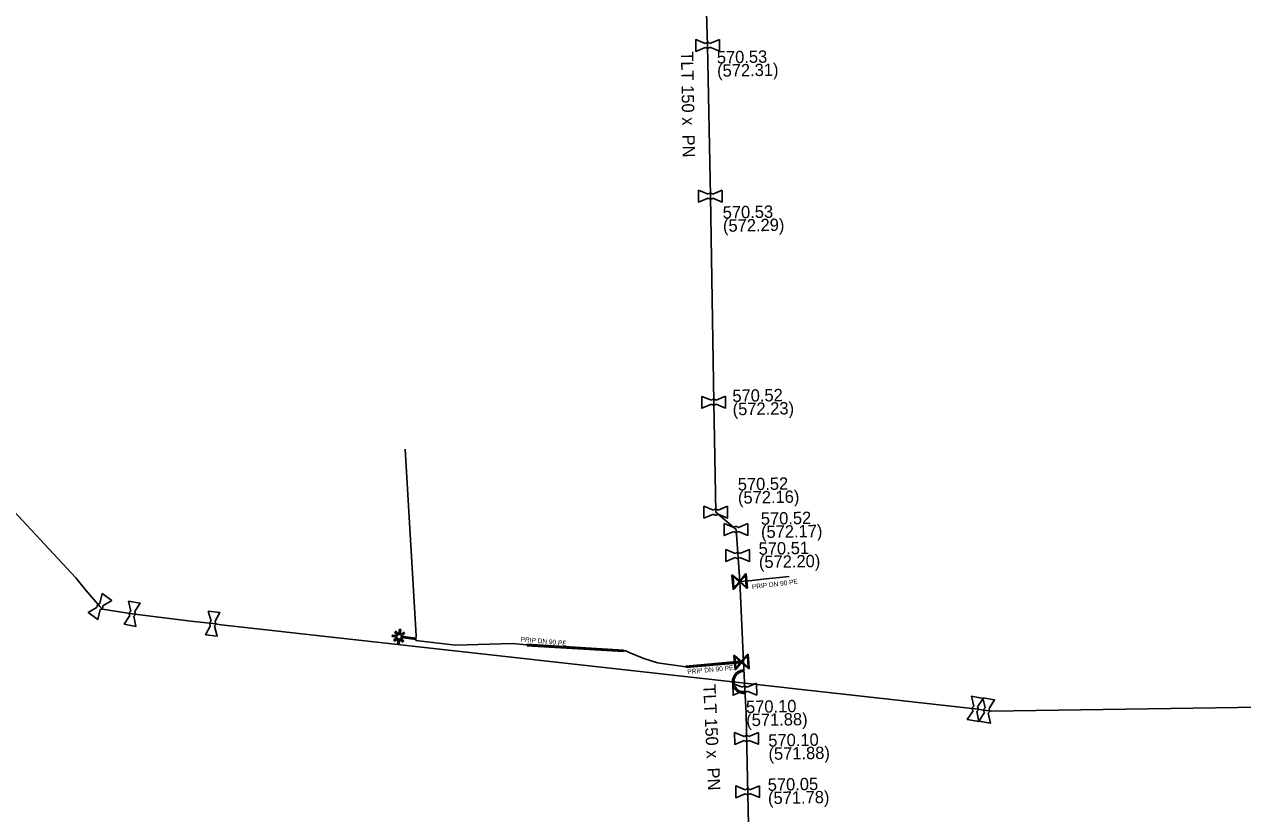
# Model space of a CAD drawing. Extents: x -643544 to -637295, y -1119190 to -1111715.
# Drawn here: x -641643.9 to -641515.4, y -1114531.6 to -1114448.4 of the extents above; entities that cross this region are included whole.
import ezdxf

# ---------------------------------------------------------------- set-up
doc = ezdxf.new("R2010")
doc.units = 0
for name, color, linetype in [('Default', 7, 'Continuous'), ('VP Chránička', 7, 'Continuous'), ('VP Chránička - okraje', 7, 'Continuous'), ('VP Lomový bod', 7, 'Continuous'), ('VP Lomový bod - popis', 7, 'Continuous'), ('VP Nepropojené křížení', 7, 'Continuous'), ('VP Popis přípojky', 7, 'Continuous'), ('VP Přípojka', 7, 'Continuous'), ('VP Změna materiálu', 7, 'Continuous'), ('VP Řad', 7, 'Continuous'), ('VP Řad - popis', 7, 'Continuous'), ('VP Šoupě', 7, 'Continuous')]:
    doc.layers.add(name, color=color, linetype=linetype)

msp = doc.modelspace()

# ---------------------------------------------------------------- linework, layer by layer
at = {"layer": 'Default'}
for points in [[(-641572.12, -1114450.39), (-641572.08, -1114450.35), (-641572.04, -1114450.32), (-641571.96, -1114450.28), (-641571.88, -1114450.28), (-641571.8, -1114450.28), (-641571.72, -1114450.32), (-641571.68, -1114450.34), (-641571.64, -1114450.38)], [(-641571.64, -1114450.79), (-641571.67, -1114450.83), (-641571.72, -1114450.86), (-641571.8, -1114450.9), (-641571.88, -1114450.9), (-641571.96, -1114450.9), (-641572.03, -1114450.86), (-641572.08, -1114450.84), (-641572.12, -1114450.8)], [(-641571.81, -1114466.29), (-641571.77, -1114466.25), (-641571.73, -1114466.22), (-641571.65, -1114466.18), (-641571.57, -1114466.18), (-641571.49, -1114466.18), (-641571.41, -1114466.22), (-641571.37, -1114466.24), (-641571.33, -1114466.28)], [(-641571.33, -1114466.69), (-641571.36, -1114466.73), (-641571.41, -1114466.76), (-641571.49, -1114466.8), (-641571.57, -1114466.8), (-641571.65, -1114466.8), (-641571.72, -1114466.76), (-641571.77, -1114466.74), (-641571.81, -1114466.7)], [(-641571.46, -1114488.03), (-641571.42, -1114487.99), (-641571.38, -1114487.96), (-641571.3, -1114487.92), (-641571.22, -1114487.92), (-641571.14, -1114487.92), (-641571.06, -1114487.96), (-641571.02, -1114487.98), (-641570.98, -1114488.02)], [(-641570.98, -1114488.43), (-641571.01, -1114488.47), (-641571.06, -1114488.5), (-641571.14, -1114488.54), (-641571.22, -1114488.54), (-641571.3, -1114488.54), (-641571.37, -1114488.5), (-641571.42, -1114488.48), (-641571.46, -1114488.44)], [(-641571.25, -1114499.63), (-641571.21, -1114499.59), (-641571.17, -1114499.56), (-641571.09, -1114499.52), (-641571.01, -1114499.52), (-641570.93, -1114499.52), (-641570.85, -1114499.56), (-641570.81, -1114499.58), (-641570.77, -1114499.62)], [(-641570.77, -1114500.03), (-641570.8, -1114500.07), (-641570.85, -1114500.1), (-641570.93, -1114500.14), (-641571.01, -1114500.14), (-641571.09, -1114500.14), (-641571.16, -1114500.1), (-641571.21, -1114500.08), (-641571.25, -1114500.04)], [(-641569.11, -1114501.46), (-641569.07, -1114501.42), (-641569.03, -1114501.39), (-641568.95, -1114501.35), (-641568.87, -1114501.35), (-641568.79, -1114501.35), (-641568.71, -1114501.39), (-641568.67, -1114501.41), (-641568.63, -1114501.45)], [(-641568.63, -1114501.86), (-641568.66, -1114501.9), (-641568.71, -1114501.93), (-641568.79, -1114501.97), (-641568.87, -1114501.97), (-641568.95, -1114501.97), (-641569.02, -1114501.93), (-641569.07, -1114501.91), (-641569.11, -1114501.87)], [(-641568.95, -1114504.2), (-641568.91, -1114504.16), (-641568.87, -1114504.13), (-641568.79, -1114504.09), (-641568.71, -1114504.09), (-641568.63, -1114504.09), (-641568.55, -1114504.13), (-641568.51, -1114504.15), (-641568.47, -1114504.19)], [(-641568.47, -1114504.6), (-641568.5, -1114504.64), (-641568.55, -1114504.67), (-641568.63, -1114504.71), (-641568.71, -1114504.71), (-641568.79, -1114504.71), (-641568.86, -1114504.67), (-641568.91, -1114504.65), (-641568.95, -1114504.61)], [(-641636.26, -1114509.85), (-641636.28, -1114509.8), (-641636.27, -1114509.75), (-641636.26, -1114509.66), (-641636.21, -1114509.6), (-641636.16, -1114509.53), (-641636.09, -1114509.49), (-641636.04, -1114509.47), (-641635.98, -1114509.47)], [(-641635.65, -1114509.71), (-641635.64, -1114509.76), (-641635.65, -1114509.81), (-641635.66, -1114509.9), (-641635.71, -1114509.96), (-641635.76, -1114510.03), (-641635.83, -1114510.06), (-641635.88, -1114510.09), (-641635.93, -1114510.09)], [(-641632.8, -1114510.74), (-641632.84, -1114510.69), (-641632.85, -1114510.64), (-641632.88, -1114510.56), (-641632.87, -1114510.48), (-641632.85, -1114510.4), (-641632.8, -1114510.34), (-641632.76, -1114510.29), (-641632.72, -1114510.27)], [(-641632.31, -1114510.34), (-641632.28, -1114510.38), (-641632.26, -1114510.43), (-641632.24, -1114510.52), (-641632.25, -1114510.6), (-641632.27, -1114510.68), (-641632.32, -1114510.74), (-641632.36, -1114510.78), (-641632.4, -1114510.81)], [(-641624.3, -1114511.8), (-641624.34, -1114511.76), (-641624.36, -1114511.71), (-641624.39, -1114511.64), (-641624.38, -1114511.55), (-641624.37, -1114511.47), (-641624.32, -1114511.4), (-641624.29, -1114511.36), (-641624.25, -1114511.33)], [(-641623.84, -1114511.38), (-641623.8, -1114511.42), (-641623.78, -1114511.46), (-641623.75, -1114511.54), (-641623.76, -1114511.63), (-641623.77, -1114511.71), (-641623.82, -1114511.77), (-641623.85, -1114511.82), (-641623.89, -1114511.85)], [(-641567.92, -1114518.96), (-641568.25, -1114518.98), (-641568.56, -1114518.83), (-641568.87, -1114518.68), (-641569.05, -1114518.39), (-641569.22, -1114518.1), (-641569.24, -1114517.78), (-641569.26, -1114517.47), (-641569.11, -1114517.16), (-641568.97, -1114516.85), (-641568.68, -1114516.67), (-641568.39, -1114516.48), (-641568.06, -1114516.47)], [(-641568.05, -1114516.62), (-641568.34, -1114516.64), (-641568.59, -1114516.8), (-641568.85, -1114516.96), (-641568.97, -1114517.23), (-641569.1, -1114517.5), (-641569.08, -1114517.77), (-641569.07, -1114518.05), (-641568.91, -1114518.3), (-641568.76, -1114518.56), (-641568.49, -1114518.69), (-641568.22, -1114518.82), (-641567.93, -1114518.81)], [(-641568.19, -1114518.3), (-641568.15, -1114518.26), (-641568.11, -1114518.23), (-641568.03, -1114518.19), (-641567.95, -1114518.19), (-641567.87, -1114518.19), (-641567.79, -1114518.23), (-641567.75, -1114518.26), (-641567.71, -1114518.3)], [(-641567.71, -1114518.71), (-641567.74, -1114518.75), (-641567.79, -1114518.77), (-641567.87, -1114518.81), (-641567.95, -1114518.82), (-641568.03, -1114518.82), (-641568.1, -1114518.77), (-641568.15, -1114518.75), (-641568.18, -1114518.71)], [(-641543.88, -1114520.78), (-641543.92, -1114520.73), (-641543.93, -1114520.68), (-641543.96, -1114520.6), (-641543.95, -1114520.52), (-641543.93, -1114520.44), (-641543.88, -1114520.38), (-641543.84, -1114520.33), (-641543.8, -1114520.31)], [(-641543.39, -1114520.38), (-641543.36, -1114520.42), (-641543.34, -1114520.47), (-641543.32, -1114520.56), (-641543.33, -1114520.64), (-641543.35, -1114520.72), (-641543.4, -1114520.78), (-641543.44, -1114520.82), (-641543.48, -1114520.85)], [(-641542.68, -1114520.95), (-641542.72, -1114520.9), (-641542.73, -1114520.85), (-641542.76, -1114520.77), (-641542.75, -1114520.69), (-641542.73, -1114520.61), (-641542.68, -1114520.55), (-641542.64, -1114520.5), (-641542.6, -1114520.48)], [(-641542.19, -1114520.55), (-641542.16, -1114520.59), (-641542.14, -1114520.64), (-641542.12, -1114520.73), (-641542.13, -1114520.81), (-641542.15, -1114520.89), (-641542.2, -1114520.95), (-641542.24, -1114520.99), (-641542.28, -1114521.02)], [(-641568, -1114523.5), (-641567.97, -1114523.46), (-641567.92, -1114523.43), (-641567.85, -1114523.39), (-641567.77, -1114523.39), (-641567.68, -1114523.39), (-641567.61, -1114523.43), (-641567.56, -1114523.45), (-641567.53, -1114523.49)], [(-641567.52, -1114523.9), (-641567.56, -1114523.94), (-641567.6, -1114523.97), (-641567.68, -1114524.01), (-641567.76, -1114524.01), (-641567.84, -1114524.01), (-641567.92, -1114523.97), (-641567.96, -1114523.94), (-641568, -1114523.9)], [(-641567.9, -1114529.12), (-641567.86, -1114529.08), (-641567.82, -1114529.05), (-641567.74, -1114529.01), (-641567.66, -1114529.01), (-641567.58, -1114529.01), (-641567.5, -1114529.05), (-641567.46, -1114529.07), (-641567.42, -1114529.11)], [(-641567.42, -1114529.52), (-641567.45, -1114529.56), (-641567.5, -1114529.59), (-641567.58, -1114529.63), (-641567.66, -1114529.63), (-641567.74, -1114529.63), (-641567.81, -1114529.59), (-641567.86, -1114529.57), (-641567.9, -1114529.53)]]:
    msp.add_open_spline(points, degree=3, dxfattribs=at)
at = {"layer": 'VP Chránička'}
for points in [[(-641590.94, -1114513.84), (-641580.73, -1114514.45)], [(-641574.16, -1114516.15), (-641568.39, -1114515.63)]]:
    msp.add_lwpolyline(points, dxfattribs=at)
at = {"layer": 'VP Chránička - okraje'}
for points in [[(-641580.73, -1114514.37), (-641590.94, -1114513.76)], [(-641580.73, -1114514.53), (-641590.94, -1114513.92)], [(-641568.4, -1114515.55), (-641574.17, -1114516.07)], [(-641568.38, -1114515.71), (-641574.15, -1114516.23)]]:
    msp.add_lwpolyline(points, dxfattribs=at)
at = {"layer": 'VP Lomový bod'}
for points in [[(-641572.12, -1114450.8), (-641573.13, -1114451.22), (-641573.13, -1114449.97), (-641572.12, -1114450.39)], [(-641570.63, -1114449.96), (-641570.63, -1114451.21), (-641571.64, -1114450.79)], [(-641571.64, -1114450.38), (-641570.63, -1114449.96)], [(-641571.81, -1114466.7), (-641572.82, -1114467.12), (-641572.82, -1114465.87), (-641571.81, -1114466.29)], [(-641570.32, -1114465.86), (-641570.32, -1114467.11), (-641571.33, -1114466.69)], [(-641571.33, -1114466.28), (-641570.32, -1114465.86)], [(-641571.46, -1114488.44), (-641572.47, -1114488.86), (-641572.47, -1114487.61), (-641571.46, -1114488.03)], [(-641569.97, -1114487.6), (-641569.97, -1114488.85), (-641570.98, -1114488.43)], [(-641570.98, -1114488.02), (-641569.97, -1114487.6)], [(-641571.25, -1114500.04), (-641572.26, -1114500.46), (-641572.26, -1114499.21), (-641571.25, -1114499.63)], [(-641569.76, -1114499.2), (-641569.76, -1114500.45), (-641570.77, -1114500.03)], [(-641570.77, -1114499.62), (-641569.76, -1114499.2)], [(-641569.11, -1114501.87), (-641570.12, -1114502.29), (-641570.12, -1114501.04), (-641569.11, -1114501.46)], [(-641567.62, -1114501.03), (-641567.62, -1114502.28), (-641568.63, -1114501.86)], [(-641568.63, -1114501.45), (-641567.62, -1114501.03)], [(-641568.95, -1114504.61), (-641569.96, -1114505.03), (-641569.96, -1114503.78), (-641568.95, -1114504.2)], [(-641567.46, -1114503.77), (-641567.46, -1114505.02), (-641568.47, -1114504.6)], [(-641568.47, -1114504.19), (-641567.46, -1114503.77)], [(-641635.98, -1114509.47), (-641635.73, -1114508.4)], [(-641635.73, -1114508.4), (-641634.72, -1114509.14), (-641635.65, -1114509.71)], [(-641635.93, -1114510.09), (-641636.19, -1114511.16), (-641637.2, -1114510.42), (-641636.26, -1114509.85)], [(-641632.95, -1114509.2), (-641631.72, -1114509.43), (-641632.31, -1114510.34)], [(-641632.72, -1114510.27), (-641632.95, -1114509.2)], [(-641632.4, -1114510.81), (-641632.17, -1114511.88), (-641633.4, -1114511.65), (-641632.8, -1114510.74)], [(-641624.55, -1114510.28), (-641623.31, -1114510.42), (-641623.84, -1114511.38)], [(-641624.25, -1114511.33), (-641624.55, -1114510.28)], [(-641623.89, -1114511.85), (-641623.59, -1114512.9), (-641624.83, -1114512.76), (-641624.3, -1114511.8)], [(-641568.18, -1114518.71), (-641569.19, -1114519.14), (-641569.2, -1114517.89), (-641568.19, -1114518.3)], [(-641566.7, -1114517.87), (-641566.69, -1114519.12), (-641567.71, -1114518.71)], [(-641567.71, -1114518.3), (-641566.7, -1114517.87)], [(-641544.03, -1114519.24), (-641542.8, -1114519.47), (-641543.39, -1114520.38)], [(-641543.8, -1114520.31), (-641544.03, -1114519.24)], [(-641542.83, -1114519.41), (-641541.6, -1114519.64), (-641542.19, -1114520.55)], [(-641542.6, -1114520.48), (-641542.83, -1114519.41)], [(-641543.48, -1114520.85), (-641543.25, -1114521.92), (-641544.48, -1114521.69), (-641543.88, -1114520.78)], [(-641542.28, -1114521.02), (-641542.05, -1114522.09), (-641543.28, -1114521.86), (-641542.68, -1114520.95)], [(-641568, -1114523.9), (-641569.01, -1114524.33), (-641569.02, -1114523.08), (-641568, -1114523.5)], [(-641567.53, -1114523.49), (-641566.52, -1114523.06)], [(-641566.52, -1114523.06), (-641566.51, -1114524.31), (-641567.52, -1114523.9)], [(-641567.9, -1114529.53), (-641568.91, -1114529.95), (-641568.91, -1114528.7), (-641567.9, -1114529.12)], [(-641566.41, -1114528.69), (-641566.41, -1114529.94), (-641567.42, -1114529.52)], [(-641567.42, -1114529.11), (-641566.41, -1114528.69)]]:
    msp.add_lwpolyline(points, dxfattribs=at)
at = {"layer": 'VP Nepropojené křížení'}
for points in [[(-641568.06, -1114516.47), (-641568.05, -1114516.62)], [(-641567.93, -1114518.81), (-641567.92, -1114518.96)]]:
    msp.add_lwpolyline(points, dxfattribs=at)
at = {"layer": 'VP Přípojka'}
for points in [[(-641603.76, -1114493.18), (-641602.6, -1114512.88), (-641602.64, -1114513.19)], [(-641568.49, -1114507.15), (-641567.52, -1114507.06), (-641566.01, -1114506.9), (-641563.26, -1114506.6)], [(-641602.64, -1114513.19), (-641602.63, -1114513.36), (-641598.47, -1114513.86), (-641592.48, -1114513.7), (-641590.94, -1114513.84), (-641580.73, -1114514.45), (-641580.51, -1114514.44), (-641580.34, -1114514.54), (-641580.14, -1114514.63), (-641578.61, -1114515.27), (-641577.14, -1114515.73), (-641574.16, -1114516.15), (-641568.39, -1114515.63), (-641568.29, -1114515.63), (-641568.09, -1114515.61)]]:
    msp.add_lwpolyline(points, dxfattribs=at)
at = {"layer": 'VP Změna materiálu'}
msp.add_lwpolyline([(-641604.59, -1114513.01), (-641605.13, -1114512.95), (-641605.11, -1114512.79), (-641604.58, -1114512.86), (-641604.87, -1114512.49), (-641604.74, -1114512.39), (-641604.46, -1114512.76), (-641604.38, -1114512.19), (-641604.23, -1114512.21), (-641604.3, -1114512.79), (-641603.93, -1114512.5), (-641603.83, -1114512.62), (-641604.2, -1114512.91), (-641602.63, -1114513.11), (-641602.65, -1114513.27), (-641604.22, -1114513.06), (-641603.94, -1114513.44), (-641604.06, -1114513.53), (-641604.35, -1114513.16), (-641604.42, -1114513.74), (-641604.58, -1114513.72), (-641604.51, -1114513.14), (-641604.87, -1114513.43), (-641604.97, -1114513.3), (-641604.59, -1114513.01)], dxfattribs=at)
at = {"layer": 'VP Řad'}
for points in [[(-641567.58, -1114533.29), (-641567.56, -1114532.76), (-641567.71, -1114526.33), (-641567.81, -1114521.06), (-641567.95, -1114518.5), (-641568.09, -1114515.61), (-641568.49, -1114507.15), (-641568.87, -1114501.66), (-641571.01, -1114499.83), (-641571.22, -1114488.23), (-641571.57, -1114466.49), (-641571.88, -1114450.59), (-641572.12, -1114442.44), (-641572.99, -1114421.12), (-641573.13, -1114416.3), (-641569.37, -1114412.33), (-641569.54, -1114406.81), (-641569.84, -1114401.36), (-641570.05, -1114397.88), (-641570.55, -1114381.19), (-641571.01, -1114366.95)], [(-641501.75, -1114520.23), (-641541.97, -1114520.82), (-641542.44, -1114520.75), (-641543.64, -1114520.58), (-641623.18, -1114511.71), (-641624.07, -1114511.59), (-641626.37, -1114511.31), (-641632.56, -1114510.54), (-641635.68, -1114510.06), (-641635.96, -1114509.78), (-641637.47, -1114508.03), (-641638.5, -1114506.77), (-641677.84, -1114464.5), (-641717.65, -1114421.76), (-641718.42, -1114421.03)]]:
    msp.add_lwpolyline(points, dxfattribs=at)
at = {"layer": 'VP Šoupě'}
for points in [[(-641567.8, -1114506.34), (-641567.68, -1114507.84), (-641567.75, -1114507.84), (-641567.84, -1114507.76), (-641568.48, -1114507.21), (-641569.11, -1114507.95), (-641569.18, -1114507.96), (-641569.3, -1114506.46), (-641569.23, -1114506.46), (-641568.49, -1114507.09), (-641567.95, -1114506.45), (-641567.87, -1114506.35), (-641567.8, -1114506.34)], [(-641569.1, -1114507.8), (-641568.55, -1114507.16), (-641569.19, -1114506.61), (-641569.1, -1114507.8)], [(-641567.88, -1114506.51), (-641568.43, -1114507.15), (-641567.79, -1114507.69), (-641567.88, -1114506.51)], [(-641567.6, -1114514.82), (-641567.48, -1114516.32), (-641567.55, -1114516.32), (-641567.64, -1114516.24), (-641568.28, -1114515.69), (-641568.91, -1114516.43), (-641568.98, -1114516.44), (-641569.1, -1114514.94), (-641569.03, -1114514.94), (-641568.29, -1114515.57), (-641567.75, -1114514.93), (-641567.67, -1114514.83), (-641567.6, -1114514.82)], [(-641568.9, -1114516.28), (-641568.35, -1114515.64), (-641568.99, -1114515.09), (-641568.9, -1114516.28)], [(-641567.68, -1114514.99), (-641568.23, -1114515.63), (-641567.59, -1114516.17), (-641567.68, -1114514.99)]]:
    msp.add_lwpolyline(points, dxfattribs=at)

# ---------------------------------------------------------------- texts
at = {"layer": 'VP Lomový bod - popis'}
for s, p in [('570.53', (-641570.89, -1114452.5)), ('(572.31)', (-641570.86, -1114453.9)), ('570.53', (-641570.27, -1114468.86)), ('(572.29)', (-641570.24, -1114470.26)), ('570.52', (-641569.25, -1114488.21)), ('(572.23)', (-641569.22, -1114489.61)), ('570.52', (-641568.68, -1114497.54)), ('(572.16)', (-641568.66, -1114498.94)), ('570.52', (-641566.25, -1114501.16)), ('(572.17)', (-641566.23, -1114502.56)), ('570.51', (-641566.48, -1114504.33)), ('(572.20)', (-641566.45, -1114505.73)), ('570.10', (-641567.81, -1114521.02)), ('(571.88)', (-641567.79, -1114522.41)), ('570.10', (-641565.46, -1114524.56)), ('(571.88)', (-641565.44, -1114525.96)), ('570.05', (-641565.52, -1114529.23)), ('(571.78)', (-641565.49, -1114530.63))]:
    msp.add_text(s, height=1.3, rotation=1, dxfattribs=at).set_placement(p)
at = {"layer": 'VP Popis přípojky'}
for rotation, p in [(6.7098, (-641567.17, -1114507.95)), (354.8056, (-641591.61, -1114513.47)), (5.1497, (-641573.99, -1114516.91))]:
    msp.add_text('PRIP DN 90 PE', height=0.5, rotation=rotation, dxfattribs=at).set_placement(p)
at = {"layer": 'VP Řad - popis'}
for rotation, p in [(271.0304, (-641574.69, -1114451.22)), (272.7267, (-641572.34, -1114518.02))]:
    msp.add_text('TLT 150 x  PN ', height=1.3, rotation=rotation, dxfattribs=at).set_placement(p)

doc.saveas('drawing.dxf')
